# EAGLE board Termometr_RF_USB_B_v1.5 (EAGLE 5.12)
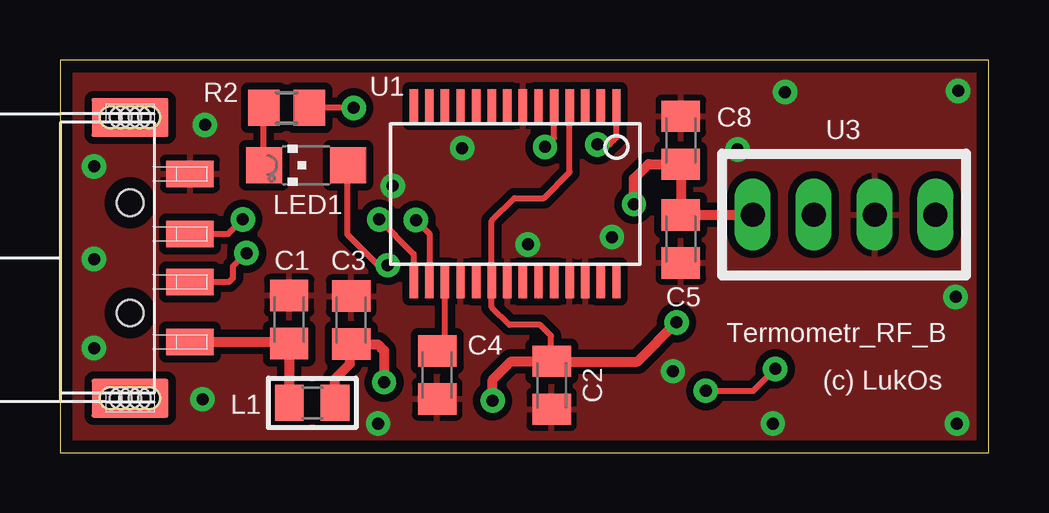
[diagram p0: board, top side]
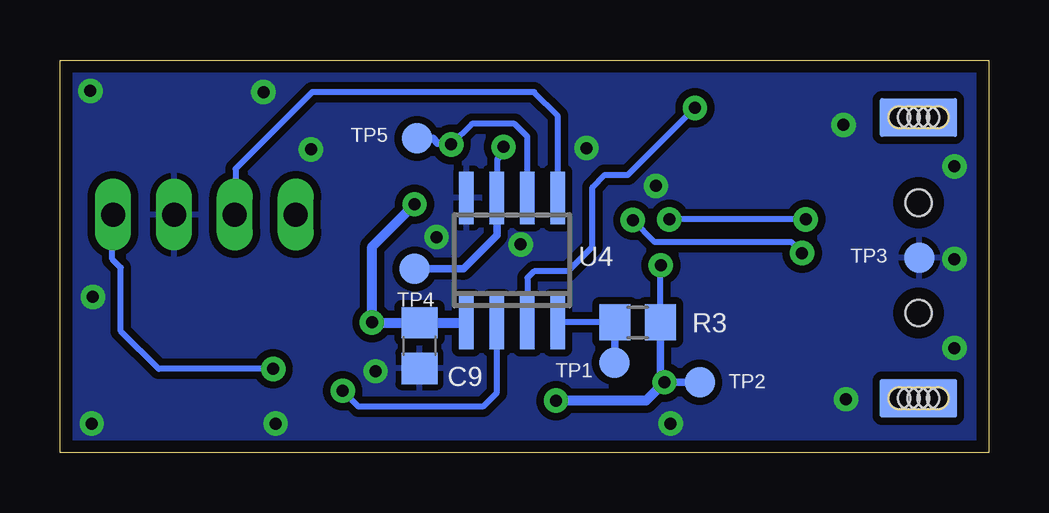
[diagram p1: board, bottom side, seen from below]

Size 38.71 x 16.37 mm. Coordinates in mm from the lower left corner, seen from the top.
Outline: 0,0 38.71,0 38.71,16.37 0,16.37 0,0
Copper layers (1*16): Top 0.035mm / dielectric 1.5mm / Bottom 0.035mm
Design rules "default *": minimum track width 10mil, minimum drill 19mil, track to track 8mil, track to pad 8mil, pad to pad 8mil, via to via 8mil, smd to smd 8mil, copper to edge 20mil, drill to drill 8mil, minimum pad ring 10mil, minimum via ring 8mil, stop-mask expansion 4mil, vias tented up to drill 0mil, thermal gap 10mil
tRestrict: area 21.5,6.8 to 21.6,7.5

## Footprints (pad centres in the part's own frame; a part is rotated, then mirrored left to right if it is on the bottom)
C0805K = smd 1.3 x 1.6: 1 -1,0; 2 1,0
C0805 = smd 1.3 x 1.5: 1 -0.95,0; 2 0.95,0
CONN_USB_A_MALE = smd 3.2 x 1.6: BODY@1 0,5.85; BODY@3 0,-5.85 | smd 3.2 x 1.6 bottom: BODY@2 0,5.85; BODY@4 0,-5.85 | smd 1.99 x 1.1: D+ -2.5,-1; D- -2.5,1; GND -2.5,-3.5; VUSB -2.5,3.5 | hole 1.1: 0,2.3; 0,-2.3 | hole 0.9: -0.8,5.85; -0.4,5.85; 0,5.85; 0.4,5.85; 0.8,5.85; -0.8,-5.85; -0.4,-5.85; 0,-5.85; 0.4,-5.85; 0.8,-5.85
L0805 = smd 1.2 x 1.5: 1 -0.953,0; 2 0.953,0
CHIPLED_1206 = smd 1.5 x 1.5: A 0,-1.75; C 0,1.75
R0805 = smd 1.3 x 1.5: 1 -0.95,0; 2 0.95,0
B1,27 = smd 1.27 x 1.27: TP 0,0
SSOP28DB = smd 0.348 x 1.397: 1 -4.225,-3.656; 2 -3.575,-3.656; 3 -2.925,-3.656; 4 -2.275,-3.656; 5 -1.625,-3.656; 6 -0.975,-3.656; 7 -0.325,-3.656; 8 0.325,-3.656; 9 0.975,-3.656; 10 1.625,-3.656; 11 2.275,-3.656; 12 2.925,-3.656; 13 3.575,-3.656; 14 4.225,-3.656; 15 4.225,3.656; 16 3.575,3.656; 17 2.925,3.656; 18 2.275,3.656; 19 1.625,3.656; 20 0.975,3.656; 21 0.325,3.656; 22 -0.325,3.656; 23 -0.975,3.656; 24 -1.625,3.656; 25 -2.275,3.656; 26 -2.925,3.656; 27 -3.575,3.656; 28 -4.225,3.656
4PIN = drill 1 long: DATA 1.27,0; EN 6.35,0; GND 3.81,0; VCC -1.27,0
SO-08 = smd 0.6 x 2.2: 1 -1.905,-2.6; 2 -0.635,-2.6; 3 0.635,-2.6; 4 1.905,-2.6; 5 1.905,2.6; 6 0.635,2.6; 7 -0.635,2.6; 8 -1.905,2.6

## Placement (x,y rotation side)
C1  100n  [C0805K]  9.55,5.56 90 top
C2  100n  [C0805K]  20.5,2.82 270 top
C3  10u  [C0805K]  12.14,5.54 90 top
C4  100n  [C0805K]  15.72,3.25 270 top
C5  100n  [C0805K]  25.88,8.92 90 top
C8  10u  [C0805K]  25.88,13.03 90 top
C9  100n  [C0805]  23.72,4.47 270 bottom
CON  USB CONN  [CONN_USB_A_MALE]  2.92,8.13 180 top
L1  FB  [L0805]  10.52,2.08 0 top
LED1  [CHIPLED_1206]  10.26,11.99 90 top
R2  560  [R0805]  9.45,14.38 180 top
R3  4.7k  [R0805]  14.63,5.44 0 bottom
TP1  PTR1B1,27  [B1,27]  15.6,3.76 0 bottom
TP2  PTR1B1,27  [B1,27]  12.04,2.95 0 bottom
TP3  PTR1B1,27  [B1,27]  2.9,8.13 0 bottom
TP4  PTR1B1,27  [B1,27]  23.93,7.67 0 bottom
TP5  PTR1B1,27  [B1,27]  23.83,13.11 0 bottom
U1  FT232RL  [SSOP28DB]  18.97,10.79 180 top
U3  HM-R868  [4PIN]  30.15,9.93 0 top
U4  PIC12F1822SN  [SO-08]  19.86,8.03 0 bottom

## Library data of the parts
C1-C5 C8 = rcl
C9 R2 R3 U1 = Luk_lib
CON = dp_devices
L1 = rc-master
LED1 = led
TP1-TP5 = testpad
U3 = hope_rf
U4 = pic12f1822

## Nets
!MCLR: R3.1 TP1.TP U4.4
+3V3: C4.1 U1.17
+5V: C2.1 C3.1 C5.2 C8.1 C9.1 L1.2 LED1.A R3.2 TP2.TP U1.4 U1.20 U3.VCC U4.1
DATA_RX: U3.DATA U4.5
EN: U3.EN U4.2
FTDI_RXD: TP4.TP U1.5 U4.7
FTDI_TXD: TP5.TP U1.1 U4.6
GND: C1.2 C2.2 C3.2 C4.2 C5.1 C8.2 C9.2 CON.GND TP3.TP U1.7 U1.18 U1.21 U1.25 U1.26 U3.GND U4.8
N$1: R2.1 U4.3
N$2: CON.D- U1.16
N$3: CON.D+ U1.15
N$4: C1.1 CON.VUSB L1.1
N$6: LED1.C R2.2

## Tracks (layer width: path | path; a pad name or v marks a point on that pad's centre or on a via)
!MCLR
  Bottom 0.254: R3.1 U4.4
  Bottom 0.305: R3.1 15.58,3.77 TP1.TP
+3V3
  Top 0.254: U1.17 16.05,4.58 C4.1 | C4.1 15.49,4.53 | C4.1 15.48,4.5 | C4.1 15.99,4.34
+5V  (via drill 0.5 pad 1.02)
  Top 0.254: C3.1 12.18,4.57 | C2.1 20.47,3.85 20.47,4.88 20.02,5.33 18.75,5.33 18,6.08 U1.20 18,9.67 18.95,10.62 20.17,10.62 21.25,11.7 U1.4 | C8.1 25.84,11.99 | 28.86,9.91 U3.VCC | v13.66,7.82 13.26,7.82 11.99,9.09 11.99,11.97 LED1.A
  Top 0.406: L1.2 11.47,3.09 12.09,3.71 12.09,4.49 C3.1 | C3.1 12.01,4.56 | C2.1 18.8,3.82 18.03,3.05 v18.03,2.18 | 28.86,9.91 C5.2 C8.1 24.54,12.04 23.93,11.43 v23.93,10.36 | C2.1 24.08,3.81 v25.7,5.44 | U3.VCC 28.91,9.91 | v13.51,2.95 13.51,4.27 13.26,4.52 12.16,4.52 C3.1
  Bottom 0.254: v25.7,5.44 25.69,5.42 | R3.2 13.68,7.81 v13.66,7.82 | U4.1
  Bottom 0.305: R3.2 13.68,3.11 v13.51,2.95 TP2.TP
  Bottom 0.406: U4.1 C9.1 25.69,5.42 25.69,8.6 v23.93,10.36 | v18.03,2.18 14.28,2.18 v13.51,2.95
DATA_RX
  Bottom 0.254: U4.5 17.96,14.05 18.95,15.04 28.19,15.04 31.39,11.84 31.39,9.96 U3.DATA
EN  (via drill 0.5 pad 1.02)
  Top 0.254: v26.92,2.59 28.91,2.59 v29.82,3.5
  Bottom 0.254: U4.2 20.5,2.52 21.08,1.93 26.26,1.93 v26.92,2.59 | v29.82,3.5 34.59,3.5 36.17,5.08 36.17,7.72 36.52,8.08 36.52,9.91 U3.EN
FTDI_RXD  (via drill 0.5 pad 1.02)
  Top 0.254: U1.5 20.6,13.13 v20.22,12.75
  Bottom 0.254: v20.22,12.75 20.22,12.5 20.47,12.24 20.47,10.65 U4.7
  Bottom 0.305: TP4.TP 21.89,7.67 20.5,9.07 U4.7
FTDI_TXD  (via drill 0.5 pad 1.02)
  Top 0.254: v22.4,12.85 22.91,12.85 23.2,13.14 U1.1
  Bottom 0.254: U4.6 19.23,13.18 19.76,13.72 21.54,13.72 v22.4,12.85
  Bottom 0.305: TP5.TP 23.16,13.11 22.96,12.9 22.45,12.9 v22.4,12.85
GND  (via drill 0.5 pad 1.02)
  other vias: 6.05,13.67 1.42,11.94 1.42,8.08 1.42,4.37 5.94,2.24 37.44,15.09 37.34,6.5 13.26,1.22 37.39,1.22 30.23,15.04 25.55,3.4 29.72,1.22 16.76,12.7 23.01,8.99 13.87,11.13 28.24,12.65 19.51,8.69
  pour Bottom (isolate 0.305): 0.15,16.18 38.51,16.18 38.51,0.13 0.18,0.13 0.15,16.13
  pour Top (isolate 0.305): 0.13,16.21 38.46,16.21 38.46,0.2 0.13,0.2 0.13,16.18
N$1  (via drill 0.5 pad 1.02)
  Top 0.254: v12.24,14.38 R2.1
  Bottom 0.254: U4.3 19.23,7.29 18.95,7.57 17.53,7.57 16.51,8.59 16.51,11.07 16,11.58 15.04,11.58 v12.24,14.38
N$2  (via drill 0.5 pad 1.02)
  Top 0.254: CON.D- 7.05,7.13 7.21,7.29 7.21,7.77 v7.77,8.33 | U1.16 15.4,9.14 v14.83,9.7
  Bottom 0.254: v7.77,8.33 8.23,8.79 13.92,8.79 v14.83,9.7
N$3  (via drill 0.5 pad 1.02)
  Top 0.254: CON.D+ 7.02,9.13 v7.62,9.73 | U1.15 14.75,8.29 v13.31,9.73
  Bottom 0.254: v7.62,9.73 v13.31,9.73
N$4
  Top 0.406: CON.VUSB 9.48,4.63 C1.1 9.55,2.1 L1.1
N$6
  Top 0.254: R2.2 8.5,12 LED1.C

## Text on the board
tNames: Termometr_RF_B | (c) LukOs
